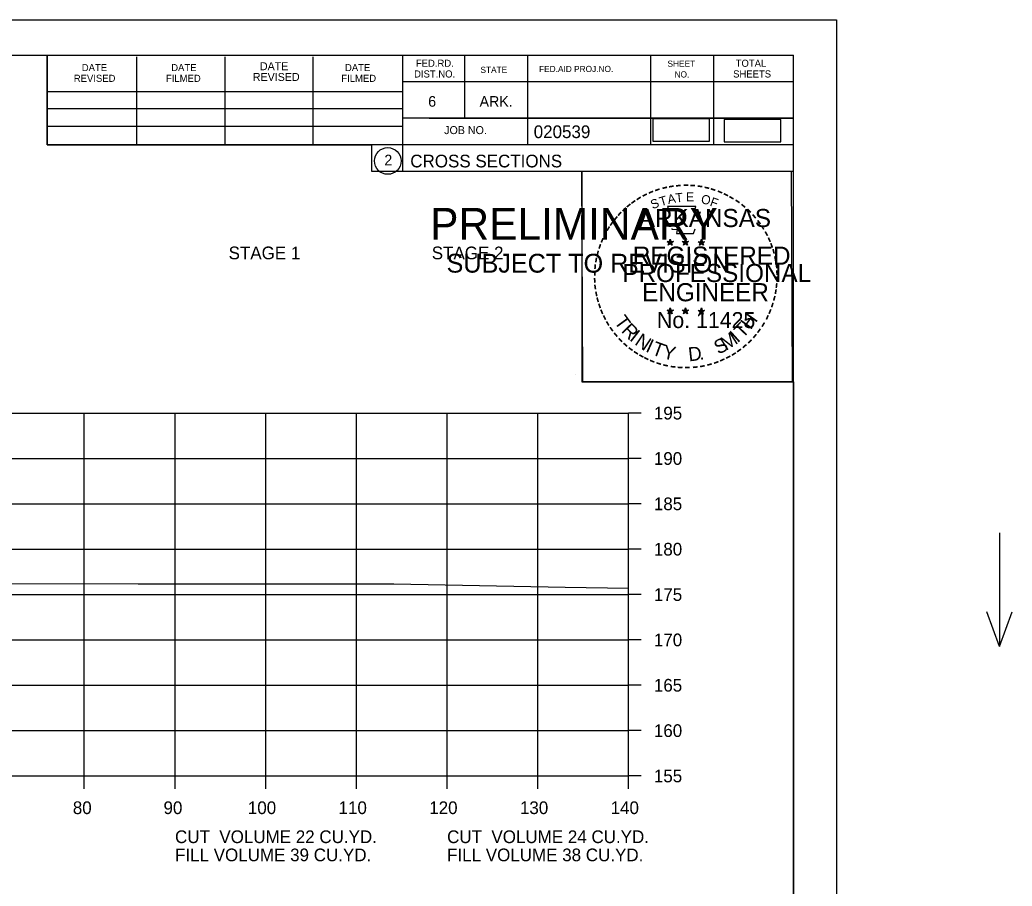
# Model space of a CAD drawing. Extents: x 915787 to 919910, y 133456 to 136717.
# Drawn here: x 916486.9 to 916596.3, y 136133.9 to 136229.4 of the extents above; entities that cross this region are included whole.
import ezdxf

# ---------------------------------------------------------------- set-up
doc = ezdxf.new("R2010")
doc.units = 0
for name, color, linetype in [('R_Axis', 7, 'Continuous'), ('R_Axis Annot', 7, 'Continuous'), ('R_Border', 7, 'Continuous'), ('R_Border Notes', 7, 'Continuous'), ('R_Border PE', 7, 'Continuous'), ('R_Border Prem', 7, 'Continuous'), ('R_Exist Surface', 7, 'Continuous'), ('R_Grid', 7, 'Continuous'), ('R_No Plot', 7, 'Continuous'), ('R_Water Annot', 7, 'Continuous'), ('R_Xsect Slope', 7, 'Continuous')]:
    doc.layers.add(name, color=color, linetype=linetype)

msp = doc.modelspace()

# ---------------------------------------------------------------- linework, layer by layer
at = {"layer": 'R_Axis'}
for p, q in [((916553.98, 136146.07), (916553.98, 136186.07)), ((916555.38, 136186.07), (916553.98, 136186.07)), ((916555.38, 136181.07), (916553.98, 136181.07)), ((916555.38, 136176.07), (916553.98, 136176.07)), ((916555.38, 136171.07), (916553.98, 136171.07)), ((916555.38, 136166.07), (916553.98, 136166.07)), ((916555.38, 136161.07), (916553.98, 136161.07)), ((916555.38, 136156.07), (916553.98, 136156.07)), ((916555.38, 136151.07), (916553.98, 136151.07)), ((916273.98, 136146.07), (916553.98, 136146.07)), ((916493.98, 136144.67), (916493.98, 136146.07)), ((916503.98, 136144.67), (916503.98, 136146.07)), ((916513.98, 136144.67), (916513.98, 136146.07)), ((916523.98, 136144.67), (916523.98, 136146.07)), ((916533.98, 136144.67), (916533.98, 136146.07)), ((916543.98, 136144.67), (916543.98, 136146.07)), ((916553.98, 136144.67), (916553.98, 136146.07)), ((916555.38, 136146.07), (916553.98, 136146.07))]:
    msp.add_line(p, q, dxfattribs=at)
at = {"layer": 'R_Border'}
for p, q in [((916255.98, 136225.53), (916572.16, 136225.53)), ((916489.9, 136215.65), (916489.9, 136225.53)), ((916499.76, 136215.65), (916499.76, 136225.33)), ((916509.52, 136215.65), (916509.52, 136225.33)), ((916519.2, 136215.65), (916519.2, 136225.33)), ((916529.06, 136225.53), (916529.06, 136212.73)), ((916535.9, 136225.53), (916535.9, 136218.59)), ((916542.84, 136225.53), (916542.84, 136215.65)), ((916556.42, 136225.53), (916556.42, 136215.65)), ((916563.36, 136225.53), (916563.36, 136215.65)), ((916572.16, 136020.07), (916572.16, 136225.53)), ((916572.16, 136222.59), (916529.06, 136222.59)), ((916572.16, 136222.61), (916572.16, 136222.61)), ((916489.9, 136221.51), (916529.06, 136221.51)), ((916489.9, 136219.65), (916529.06, 136219.65)), ((916572.16, 136218.59), (916529.06, 136218.59)), ((916532.02, 136218.59), (916572.16, 136218.59)), ((916489.9, 136215.65), (916489.9, 136217.71)), ((916489.9, 136217.71), (916529.06, 136217.71)), ((916572.16, 136215.65), (916489.9, 136215.65)), ((916529.06, 136212.73), (916572.16, 136212.73))]:
    msp.add_line(p, q, dxfattribs=at)
msp.add_circle((916527.44, 136213.87), 1.47, dxfattribs=at)
at = {"layer": 'R_Border PE'}
for p, q in [((916558.24, 136204.99), (916558.59, 136204.87)), ((916558.24, 136204.99), (916558.49, 136204.94)), ((916558.24, 136204.99), (916558.48, 136204.86)), ((916558.37, 136204.58), (916558.59, 136204.87)), ((916558.37, 136204.58), (916558.5, 136204.82)), ((916558.59, 136205.24), (916558.55, 136204.99)), ((916558.59, 136204.87), (916558.59, 136205.24)), ((916558.59, 136205.24), (916558.64, 136204.99)), ((916558.94, 136204.99), (916558.59, 136204.87)), ((916558.8, 136204.58), (916558.59, 136204.87)), ((916558.94, 136204.99), (916558.65, 136204.94)), ((916558.8, 136204.58), (916558.66, 136204.87)), ((916558.94, 136204.99), (916558.73, 136204.88)), ((916559.91, 136204.99), (916560.26, 136204.87)), ((916559.91, 136204.99), (916560.16, 136204.94)), ((916559.91, 136204.99), (916560.15, 136204.86)), ((916560.04, 136204.58), (916560.26, 136204.87)), ((916560.04, 136204.58), (916560.17, 136204.82)), ((916560.26, 136205.24), (916560.22, 136204.99)), ((916560.26, 136204.87), (916560.26, 136205.24)), ((916560.26, 136205.24), (916560.31, 136204.99)), ((916560.61, 136204.99), (916560.26, 136204.87)), ((916560.47, 136204.58), (916560.26, 136204.87)), ((916560.61, 136204.99), (916560.32, 136204.94)), ((916560.47, 136204.58), (916560.33, 136204.87)), ((916560.61, 136204.99), (916560.4, 136204.88)), ((916561.67, 136204.97), (916562.02, 136204.86)), ((916561.67, 136204.97), (916561.93, 136204.93)), ((916561.67, 136204.97), (916561.91, 136204.85)), ((916561.81, 136204.57), (916562.02, 136204.86)), ((916561.81, 136204.57), (916561.93, 136204.81)), ((916562.02, 136205.23), (916561.98, 136204.98)), ((916562.02, 136204.86), (916562.02, 136205.23)), ((916562.02, 136205.23), (916562.07, 136204.98)), ((916562.37, 136204.97), (916562.02, 136204.86)), ((916562.24, 136204.57), (916562.02, 136204.86)), ((916562.37, 136204.97), (916562.08, 136204.92)), ((916562.24, 136204.57), (916562.1, 136204.86)), ((916562.37, 136204.97), (916562.17, 136204.87)), ((916558.37, 136204.58), (916558.59, 136204.79)), ((916558.8, 136204.58), (916558.59, 136204.79)), ((916560.04, 136204.58), (916560.26, 136204.79)), ((916560.47, 136204.58), (916560.26, 136204.79)), ((916561.81, 136204.57), (916562.02, 136204.78)), ((916562.24, 136204.57), (916562.02, 136204.78)), ((916558.24, 136197.41), (916558.58, 136197.3)), ((916558.24, 136197.41), (916558.49, 136197.37)), ((916558.24, 136197.41), (916558.47, 136197.29)), ((916558.37, 136197), (916558.58, 136197.3)), ((916558.37, 136197), (916558.49, 136197.25)), ((916558.37, 136197), (916558.58, 136197.22)), ((916558.58, 136197.67), (916558.54, 136197.41)), ((916558.58, 136197.3), (916558.58, 136197.67)), ((916558.58, 136197.67), (916558.63, 136197.42)), ((916558.93, 136197.41), (916558.58, 136197.3)), ((916558.8, 136197), (916558.58, 136197.3)), ((916558.8, 136197), (916558.58, 136197.22)), ((916558.93, 136197.41), (916558.65, 136197.36)), ((916558.8, 136197), (916558.66, 136197.3)), ((916558.93, 136197.41), (916558.73, 136197.31)), ((916559.9, 136197.41), (916560.25, 136197.3)), ((916559.9, 136197.41), (916560.16, 136197.37)), ((916559.9, 136197.41), (916560.14, 136197.29)), ((916560.04, 136197), (916560.25, 136197.3)), ((916560.04, 136197), (916560.16, 136197.25)), ((916560.04, 136197), (916560.25, 136197.22)), ((916560.25, 136197.67), (916560.21, 136197.41)), ((916560.25, 136197.3), (916560.25, 136197.67)), ((916560.25, 136197.67), (916560.3, 136197.42)), ((916560.6, 136197.41), (916560.25, 136197.3)), ((916560.47, 136197), (916560.25, 136197.3)), ((916560.47, 136197), (916560.25, 136197.22)), ((916560.6, 136197.41), (916560.31, 136197.36)), ((916560.47, 136197), (916560.33, 136197.3)), ((916560.6, 136197.41), (916560.4, 136197.31)), ((916561.67, 136197.4), (916562.02, 136197.29)), ((916561.67, 136197.4), (916561.92, 136197.36)), ((916561.67, 136197.4), (916561.91, 136197.28)), ((916561.8, 136196.99), (916562.02, 136197.29)), ((916561.8, 136196.99), (916561.93, 136197.24)), ((916561.8, 136196.99), (916562.02, 136197.21)), ((916562.02, 136197.66), (916561.98, 136197.4)), ((916562.02, 136197.29), (916562.02, 136197.66)), ((916562.02, 136197.66), (916562.07, 136197.41)), ((916562.37, 136197.4), (916562.02, 136197.29)), ((916562.23, 136196.99), (916562.02, 136197.29)), ((916562.23, 136196.99), (916562.02, 136197.21)), ((916562.37, 136197.4), (916562.08, 136197.35)), ((916562.23, 136196.99), (916562.1, 136197.29)), ((916562.37, 136197.4), (916562.16, 136197.3))]:
    msp.add_line(p, q, dxfattribs=at)
for points in [[(916558.28, 136208.86), (916558.55, 136208.04)], [(916561.79, 136207.94), (916561.93, 136208.23), (916561.25, 136208.2), (916561.4, 136208.86), (916558.28, 136208.86)], [(916558.77, 136206.44), (916558.77, 136206.35), (916559.34, 136206.33), (916559.28, 136205.86), (916561.15, 136205.86), (916561.35, 136206.4)], [(916558.59, 136205.24), (916558.8, 136204.58), (916558.24, 136204.99), (916558.94, 136204.99), (916558.37, 136204.58), (916558.59, 136205.24)], [(916560.26, 136205.24), (916560.47, 136204.58), (916559.91, 136204.99), (916560.61, 136204.99), (916560.04, 136204.58), (916560.26, 136205.24)], [(916562.02, 136205.23), (916562.24, 136204.57), (916561.67, 136204.97), (916562.37, 136204.97), (916561.81, 136204.57), (916562.02, 136205.23)], [(916558.58, 136197.67), (916558.8, 136197), (916558.24, 136197.41), (916558.93, 136197.41), (916558.37, 136197), (916558.58, 136197.67)], [(916560.25, 136197.67), (916560.47, 136197), (916559.9, 136197.41), (916560.6, 136197.41), (916560.04, 136197), (916560.25, 136197.67)], [(916562.02, 136197.66), (916562.23, 136196.99), (916561.67, 136197.4), (916562.37, 136197.4), (916561.8, 136196.99), (916562.02, 136197.66)]]:
    msp.add_lwpolyline(points, dxfattribs=at)
for centre, radius in [((916558.59, 136204.87), 0.172), ((916558.59, 136204.87), 0.145), ((916558.59, 136204.87), 0.116), ((916558.59, 136204.87), 0.0991), ((916558.59, 136204.87), 0.0747), ((916558.59, 136204.87), 0.0495), ((916558.59, 136204.87), 0.0296), ((916560.26, 136204.87), 0.172), ((916560.26, 136204.87), 0.145), ((916560.26, 136204.87), 0.116), ((916560.26, 136204.87), 0.0991), ((916560.26, 136204.87), 0.0747), ((916560.26, 136204.87), 0.0495), ((916560.26, 136204.87), 0.0296), ((916562.02, 136204.86), 0.172), ((916562.02, 136204.86), 0.145), ((916562.02, 136204.86), 0.116), ((916562.02, 136204.86), 0.0991), ((916562.02, 136204.86), 0.0747), ((916562.02, 136204.86), 0.0495), ((916562.02, 136204.86), 0.0296), ((916558.58, 136197.3), 0.172), ((916558.58, 136197.3), 0.145), ((916558.58, 136197.3), 0.116), ((916558.58, 136197.3), 0.0991), ((916558.58, 136197.3), 0.0747), ((916558.58, 136197.3), 0.0495), ((916558.58, 136197.3), 0.0296), ((916560.25, 136197.3), 0.172), ((916560.25, 136197.3), 0.145), ((916560.25, 136197.3), 0.116), ((916560.25, 136197.3), 0.0991), ((916560.25, 136197.3), 0.0747), ((916560.25, 136197.3), 0.0495), ((916560.25, 136197.3), 0.0296), ((916562.02, 136197.29), 0.172), ((916562.02, 136197.29), 0.145), ((916562.02, 136197.29), 0.116), ((916562.02, 136197.29), 0.0991), ((916562.02, 136197.29), 0.0747), ((916562.02, 136197.29), 0.0495), ((916562.02, 136197.29), 0.0296)]:
    msp.add_circle(centre, radius, dxfattribs=at)
at = {"layer": 'R_Exist Surface'}
msp.add_lwpolyline([(916483.32, 136167.3), (916499.92, 136167.25), (916508.82, 136167.25), (916528.1, 136167.25), (916547, 136166.9), (916553.98, 136166.77)], dxfattribs=at)
at = {"layer": 'R_Grid'}
for p, q in [((916273.98, 136186.07), (916553.98, 136186.07)), ((916493.98, 136146.07), (916493.98, 136186.07)), ((916503.98, 136146.07), (916503.98, 136186.07)), ((916513.98, 136146.07), (916513.98, 136186.07)), ((916523.98, 136146.07), (916523.98, 136186.07)), ((916533.98, 136146.07), (916533.98, 136186.07)), ((916543.98, 136146.07), (916543.98, 136186.07)), ((916553.98, 136146.07), (916553.98, 136186.07)), ((916273.98, 136181.07), (916553.98, 136181.07)), ((916273.98, 136176.07), (916553.98, 136176.07)), ((916273.98, 136171.07), (916553.98, 136171.07)), ((916273.98, 136166.07), (916553.98, 136166.07)), ((916273.98, 136161.07), (916553.98, 136161.07)), ((916273.98, 136156.07), (916553.98, 136156.07)), ((916273.98, 136151.07), (916553.98, 136151.07)), ((916273.98, 136146.07), (916553.98, 136146.07))]:
    msp.add_line(p, q, dxfattribs=at)
at = {"layer": 'R_No Plot'}
for p, q in [((916243.57, 136229.43), (916576.91, 136229.43)), ((916548.19, 136190.28), (916548.19, 136190.28))]:
    msp.add_line(p, q, dxfattribs=at)
for points in [[(916243.57, 136229.43), (916576.91, 136229.43), (916576.91, 136016.09), (916243.57, 136016.09)], [(916489.9, 136225.53), (916489.9, 136215.65), (916525.63, 136215.65), (916525.63, 136212.73), (916548.83, 136212.73), (916548.83, 136189.52), (916572.16, 136189.52), (916572.16, 136020.07), (916255.98, 136020.07), (916255.98, 136225.53)], [(916548.83, 136212.76), (916571.92, 136212.76), (916572.04, 136189.52), (916548.94, 136189.52)]]:
    msp.add_lwpolyline(points, close=True, dxfattribs=at)
at = {"layer": 'R_Water Annot'}
for p, q in [((916594.88, 136172.89), (916594.88, 136160.33)), ((916594.88, 136160.33), (916593.48, 136164.17)), ((916594.88, 136160.33), (916596.28, 136164.17))]:
    msp.add_line(p, q, dxfattribs=at)
at = {"layer": 'R_Xsect Slope'}
for points in [[(916556.68, 136216.06), (916562.93, 136216.06), (916562.93, 136218.53), (916556.68, 136218.53)], [(916564.53, 136215.97), (916570.78, 136215.97), (916570.78, 136218.44), (916564.53, 136218.44)]]:
    msp.add_lwpolyline(points, close=True, dxfattribs=at)

# ---------------------------------------------------------------- texts
at = {"layer": 'R_Axis Annot'}
for s, p in [('195', (916556.78, 136185.37)), ('190', (916556.78, 136180.37)), ('185', (916556.78, 136175.37)), ('180', (916556.78, 136170.37)), ('175', (916556.78, 136165.37)), ('170', (916556.78, 136160.37)), ('165', (916556.78, 136155.37)), ('160', (916556.78, 136150.37)), ('155', (916556.78, 136145.37)), ('80', (916492.71, 136141.87)), ('90', (916502.71, 136141.87)), ('100', (916512.01, 136141.87)), ('110', (916522.01, 136141.87)), ('120', (916532.01, 136141.87)), ('130', (916542.01, 136141.87)), ('140', (916552.01, 136141.87))]:
    msp.add_text(s, height=1.4, dxfattribs=at).set_placement(p)
at = {"layer": 'R_Border'}
for s, height, p in [('DATE', 0.782, (916493.7, 136223.77)), ('DATE', 0.782, (916503.56, 136223.77)), ('DATE', 0.879, (916513.34, 136223.87)), ('DATE', 0.782, (916522.72, 136223.77)), ('FED.RD.', 0.782, (916530.54, 136224.25)), ('SHEET', 0.684, (916558.28, 136224.25)), ('TOTAL', 0.782, (916565.8, 136224.25)), ('REVISED', 0.879, (916512.56, 136222.69)), ('DIST.NO.', 0.782, (916530.34, 136223.07)), ('STATE', 0.684, (916537.66, 136223.57)), ('FED.AID PROJ.NO.', 0.684, (916544.12, 136223.67)), ('NO.', 0.684, (916559.06, 136223.07)), ('SHEETS', 0.782, (916565.52, 136223.07)), ('REVISED', 0.782, (916492.82, 136222.59)), ('FILMED', 0.782, (916502.98, 136222.59)), ('FILMED', 0.782, (916522.32, 136222.59)), ('6', 1.17, (916531.9, 136219.85)), ('ARK.', 1.172, (916537.56, 136219.85)), ('JOB NO.', 0.879, (916533.66, 136216.83)), ('020539', 1.4, (916543.53, 136216.39)), ('2', 1.17, (916527.06, 136213.38)), ('CROSS SECTIONS', 1.4, (916529.92, 136213.16))]:
    msp.add_text(s, height=height, rotation=360, dxfattribs=at).set_placement(p)
at = {"layer": 'R_Border Notes'}
for s, p in [('STAGE 1', (916509.89, 136203.03)), ('STAGE 2', (916532.29, 136203.03)), ('CUT  VOLUME 22 CU.YD.', (916503.98, 136138.67)), ('CUT  VOLUME 24 CU.YD.', (916533.98, 136138.67)), ('FILL VOLUME 39 CU.YD.', (916503.98, 136136.67)), ('FILL VOLUME 38 CU.YD.', (916533.98, 136136.67))]:
    msp.add_text(s, height=1.4, dxfattribs=at).set_placement(p)
at = {"layer": 'R_Border PE'}
for s, height, rotation, p in [('-', 1.6, 28.7918, (916555.76, 136209.4)), ('-', 1.6, 24.3072, (916556.39, 136209.72)), ('-', 1.6, 19.1761, (916557.03, 136209.99)), ('-', 1.6, 13.6301, (916557.78, 136210.23)), ('-', 1.6, 10.2193, (916558.46, 136210.39)), ('T', 1, 6.0228, (916559.22, 136209.29)), ('-', 1.6, 5.8968, (916559.19, 136210.5)), ('-', 1.6, 0.1862, (916559.96, 136210.58)), ('E', 1, 0.8323, (916560.33, 136209.4)), ('-', 1.6, 357.743, (916560.68, 136210.56)), ('-', 1.6, 352.1617, (916561.42, 136210.51)), ('-', 1.6, 347.2049, (916562.14, 136210.39)), ('-', 1.6, 342.3362, (916562.78, 136210.24)), ('-', 1.6, 337.8551, (916563.51, 136210.01)), ('-', 1.6, 334.1211, (916564.14, 136209.74)), ('-', 1.6, 38.9507, (916554.11, 136208.26)), ('-', 1.6, 36.2317, (916554.59, 136208.64)), ('-', 1.6, 34.0636, (916555.16, 136209.03)), ('S', 1, 21.594, (916556.64, 136208.54)), ('T', 1, 16.4036, (916557.55, 136208.87)), ('A', 1, 11.2132, (916558.38, 136209.12)), ('O', 1, 350.4515, (916561.93, 136209.19)), ('F', 1, 340.0707, (916562.89, 136208.96)), ('-', 1.6, 329.6409, (916564.72, 136209.46)), ('-', 1.6, 325.8627, (916565.37, 136209.1)), ('-', 1.6, 48.423, (916553.23, 136207.37)), ('-', 1.6, 42.9622, (916553.68, 136207.84)), ('ARKANSAS', 2, 360, (916555.13, 136206.58)), ('-', 1.6, 320.5297, (916565.98, 136208.67)), ('-', 1.6, 315.5786, (916566.58, 136208.19)), ('-', 1.6, 54.2325, (916552.41, 136206.31)), ('-', 1.6, 50.6142, (916552.83, 136206.88)), ('-', 1.6, 309.8797, (916567.14, 136207.64)), ('-', 1.6, 306.6522, (916567.67, 136207.03)), ('-', 1.6, 62.8713, (916551.78, 136205.17)), ('-', 1.6, 58.0706, (916552.09, 136205.79)), ('-', 1.4, 303.6753, (916568.16, 136206.47)), ('-', 1.6, 299.6684, (916568.47, 136205.86)), ('-', 1.6, 67.7743, (916551.52, 136204.56)), ('DWB', 0.01, 360, (916558.58, 136204.87)), ('DWB', 0.01, 360, (916560.25, 136204.87)), ('DWB', 0.01, 360, (916562.01, 136204.86)), ('-', 1.6, 294.6628, (916568.8, 136205.25)), ('-', 1.6, 290.5728, (916569.06, 136204.67)), ('-', 1.6, 75.461, (916551.1, 136203.22)), ('-', 1.6, 72.3945, (916551.3, 136203.93)), ('REGISTERED', 2, 360, (916554.46, 136202.43)), ('-', 1.6, 285.1233, (916569.29, 136204.09)), ('-', 1.6, 81.2013, (916550.97, 136202.5)), ('-', 1.6, 280.5493, (916569.49, 136203.35)), ('-', 1.6, 89.0622, (916550.87, 136201.11)), ('-', 1.6, 85.1863, (916550.89, 136201.81)), ('PROFESSIONAL', 2, 360, (916553.31, 136200.52)), ('-', 1.6, 276.5962, (916569.65, 136202.58)), ('-', 1.6, 274.3301, (916569.71, 136201.86)), ('-', 1.6, 94.1959, (916550.9, 136200.39)), ('ENGINEER', 2, 360, (916555.49, 136198.4)), ('-', 1.6, 269.9407, (916569.75, 136201.23)), ('-', 1.6, 98.9479, (916550.97, 136199.72)), ('-', 1.6, 101.7149, (916551.11, 136198.99)), ('-', 1.6, 260.9953, (916569.66, 136199.91)), ('-', 1.6, 263.5172, (916569.73, 136200.56)), ('-', 1.6, 105.4578, (916551.27, 136198.39)), ('-', 1.6, 252.8681, (916569.36, 136198.51)), ('-', 1.6, 255.7626, (916569.55, 136199.23)), ('-', 1.6, 109.0874, (916551.49, 136197.76)), ('-', 1.6, 114.0643, (916551.74, 136197.17)), ('No. 11425', 1.757, 360, (916557.12, 136195.45)), ('DWB', 0.01, 360, (916558.57, 136197.3)), ('DWB', 0.01, 360, (916560.24, 136197.3)), ('DWB', 0.01, 360, (916562.01, 136197.29)), ('H', 1.54, 54.6088, (916567.46, 136195.18)), ('-', 1.6, 247.8887, (916569.14, 136197.83)), ('-', 1.6, 115.7289, (916552.05, 136196.55)), ('-', 1.6, 120.4471, (916552.4, 136195.96)), ('T', 1.54, 306.0406, (916552.34, 136196.14)), ('T', 1.54, 46.6444, (916566.58, 136194.23)), ('-', 1.6, 239.0712, (916568.49, 136196.45)), ('-', 1.6, 244.6197, (916568.88, 136197.21)), ('-', 1.6, 125.8934, (916552.81, 136195.4)), ('-', 1.6, 130.7181, (916553.27, 136194.85)), ('R', 1.54, 314.005, (916553.11, 136195.09)), ('I', 1.54, 321.9694, (916554.01, 136194.16)), ('M', 1.54, 32.6563, (916564.73, 136192.91)), ('I', 1.54, 42.1136, (916566.01, 136193.75)), ('-', 1.6, 233.8452, (916568.08, 136195.8)), ('-', 1.6, 134.2238, (916553.78, 136194.3)), ('N', 1.54, 326.5002, (916554.57, 136193.69)), ('I', 1.54, 335.3603, (916555.78, 136192.9)), ('T', 1.54, 339.8912, (916556.44, 136192.58)), ('S', 1.54, 26.9312, (916563.89, 136192.5)), ('-', 1.6, 225.7653, (916567.17, 136194.67)), ('-', 1.6, 231.2538, (916567.65, 136195.23)), ('-', 1.6, 138.9338, (916554.31, 136193.84)), ('-', 1.6, 144.6463, (916554.87, 136193.43)), ('-', 1.6, 148.0898, (916555.43, 136193.06)), ('Y', 1.54, 347.8556, (916557.66, 136192.13)), ('D', 1.54, 6.3969, (916560.65, 136191.77)), ('-', 1.6, 212.2491, (916565.57, 136193.3)), ('-', 1.6, 215.7363, (916566.1, 136193.69)), ('-', 1.6, 221.0851, (916566.65, 136194.16)), ('-', 1.6, 151.5704, (916556.01, 136192.74)), ('-', 1.6, 154.6002, (916556.53, 136192.49)), ('-', 1.6, 158.5612, (916557.15, 136192.24)), ('-', 1.6, 162.7983, (916557.84, 136192.02)), ('.', 1.54, 13.7642, (916561.84, 136191.9)), ('-', 1.6, 200.7184, (916563.77, 136192.36)), ('-', 1.6, 204.2516, (916564.39, 136192.64)), ('-', 1.6, 207.3568, (916565.01, 136192.96)), ('-', 1.6, 167.5555, (916558.55, 136191.86)), ('-', 1.6, 173.1155, (916559.33, 136191.75)), ('-', 1.6, 176.5183, (916560.07, 136191.7)), ('-', 1.6, 181.5918, (916560.82, 136191.72)), ('-', 1.6, 185.8167, (916561.63, 136191.79)), ('-', 1.6, 191.2858, (916562.36, 136191.92)), ('-', 1.6, 195.4743, (916563.09, 136192.12))]:
    msp.add_text(s, height=height, rotation=rotation, dxfattribs=at).set_placement(p)
at = {"layer": 'R_Border Prem'}
for s, height, p in [('PRELIMINARY', 3.5, (916532.11, 136205.19)), ('DWB', 0.01, (916532.85, 136207.04)), ('SUBJECT TO REVISION', 2.0751, (916533.92, 136201.56))]:
    msp.add_text(s, height=height, rotation=360, dxfattribs=at).set_placement(p)

doc.saveas('drawing.dxf')
